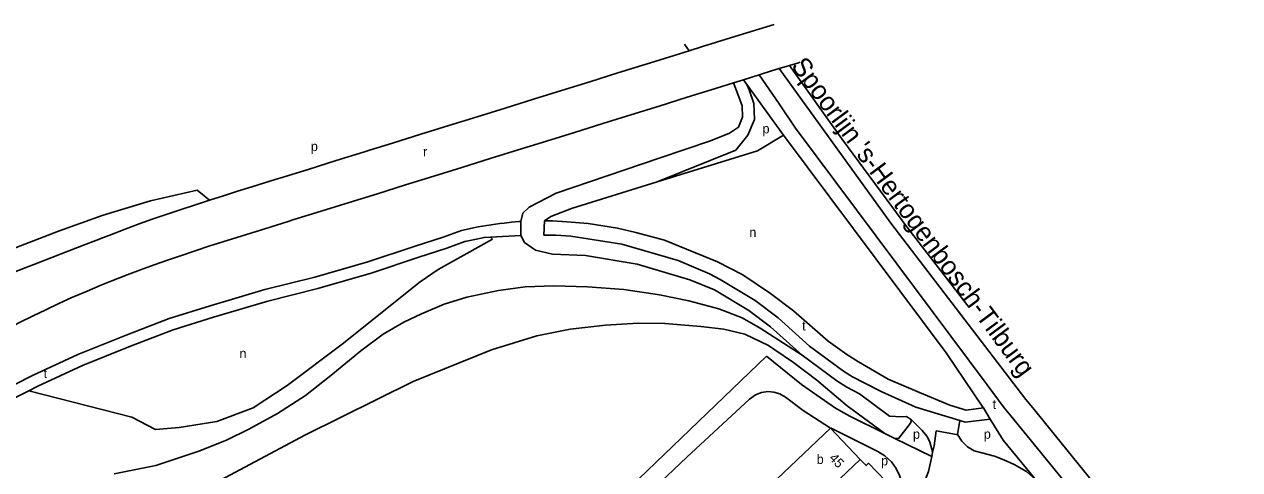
# Model space of a CAD drawing. Extents: x 156097 to 158136, y 385644 to 388348.
# Drawn here: x 156439 to 156955, y 388159 to 388348 of the extents above; entities that cross this region are included whole.
import ezdxf

# ---------------------------------------------------------------- set-up
doc = ezdxf.new("R2010")
doc.units = 0
for name, color, linetype in [('BLT_Basislijn', 7, 'Continuous'), ('BLT_Bebouwing', 7, 'Continuous'), ('BLT_Centroide', 7, 'Continuous'), ('BLT_Huisnummer_zonder_bebouwing', 7, 'Continuous'), ('BLT_Spoorlijn', 7, 'Continuous'), ('BLT_Vlakafsluiter', 7, 'Continuous'), ('BLT_Waternaam_spoorwegen', 7, 'Continuous')]:
    doc.layers.add(name, color=color, linetype=linetype)

msp = doc.modelspace()

# ---------------------------------------------------------------- linework, layer by layer
at = {"layer": 'BLT_Basislijn'}
for p, q in [((156719.27, 388339.5), (156721.23, 388336.66)), ((156740.1, 388323.1), (156744.33, 388324.41)), ((156744.33, 388324.41), (156750.98, 388326.48)), ((156744.33, 388324.41), (156745.73, 388322.47)), ((156745.73, 388322.47), (156761.29, 388300.94)), ((156761.29, 388300.94), (156750.28, 388294.39)), ((156750.28, 388294.39), (156707.78, 388281.17)), ((156707.78, 388281.17), (156671.38, 388269.85)), ((156649.88, 388258.43), (156649.94, 388264.43)), ((156659.75, 388258.63), (156660.01, 388264.72)), ((156634.36, 388257.66), (156637.13, 388257.8)), ((156637.13, 388257.8), (156637.97, 388256.94)), ((156836.05, 388180.16), (156820.66, 388184.84)), ((156838.7, 388184.58), (156846.02, 388185.48)), ((156845.79, 388185.85), (156846.02, 388185.48)), ((156835.07, 388174.23), (156836.05, 388180.16)), ((156838.25, 388179.49), (156848.88, 388180.8)), ((156808.46, 388172.56), (156804.17, 388174.7)), ((156808.46, 388172.56), (156824.09, 388164.9)), ((156824.48, 388166.58), (156824.09, 388164.9))]:
    msp.add_line(p, q, dxfattribs=at)
for points in [[(156721.23, 388336.66), (156726.88, 388338.42), (156738.82, 388342.13), (156750.76, 388345.84), (156757.28, 388347.86)], [(156517.96, 388273.44), (156523.93, 388275.34), (156529.91, 388277.22), (156535.88, 388279.08), (156540.87, 388280.63), (156545.86, 388282.17), (156547.83, 388282.78), (156559.77, 388286.48), (156571.71, 388290.19), (156583.64, 388293.9), (156585.78, 388294.56), (156595.58, 388297.61), (156607.52, 388301.32), (156615.33, 388303.74), (156619.45, 388305.03), (156631.39, 388308.74), (156643.33, 388312.45), (156655.26, 388316.16), (156667.2, 388319.87), (156679.14, 388323.58), (156691.07, 388327.29), (156703.01, 388331), (156714.95, 388334.71), (156721.23, 388336.66)], [(156750.98, 388326.48), (156756.26, 388328.12), (156759.46, 388329.12)], [(156759.46, 388329.12), (156762.84, 388330.16), (156763.75, 388330.45)], [(156763.75, 388330.45), (156767.58, 388331.64), (156768.38, 388331.9)], [(156750.98, 388326.48), (156759.42, 388314.15), (156766.39, 388303.96)], [(156601.09, 388279.89), (156613.02, 388283.6), (156620.83, 388286.03), (156624.96, 388287.31), (156636.9, 388291.02), (156648.83, 388294.73), (156660.77, 388298.44), (156672.71, 388302.15), (156684.64, 388305.86), (156696.58, 388309.57), (156708.52, 388313.28), (156720.45, 388316.99), (156732.39, 388320.7), (156740.1, 388323.1)], [(156740.1, 388323.1), (156741.99, 388318.36), (156743.77, 388313.39), (156743.96, 388308.52), (156742.18, 388304.31), (156738.43, 388301.78), (156730.38, 388298.59), (156708.65, 388291.19), (156664.98, 388276.43)], [(156707.78, 388281.17), (156741.07, 388294.57), (156746.21, 388301), (156749, 388307.6), (156748.74, 388314.36), (156746.67, 388320.13), (156745.73, 388322.47)], [(156766.39, 388303.96), (156809.26, 388246.5), (156847.59, 388195.26), (156854.85, 388185.54), (156857.58, 388182.14), (156915.93, 388110.8)], [(156761.29, 388300.94), (156830.24, 388208.76), (156845.79, 388185.85)], [(156310.15, 388191.73), (156310.04, 388198.76), (156310.36, 388202.13), (156311, 388204.11), (156312.29, 388205.67), (156314.27, 388206.74), (156318.97, 388208.56), (156330.61, 388213.22), (156351.21, 388221.28), (156374.15, 388230.36), (156403.23, 388241.32), (156427.16, 388250.01), (156454.03, 388260.34), (156472.88, 388267.06), (156493.03, 388273.12), (156512.7, 388277.71)], [(156462.79, 388233.54), (156466.12, 388234.99), (156471.72, 388237.34), (156476.63, 388239.32), (156479.82, 388240.57), (156483.03, 388241.8), (156488.74, 388243.94), (156494.49, 388246.03), (156500.26, 388248.06), (156506.07, 388250.05), (156511.91, 388252), (156517.77, 388253.91), (156523.65, 388255.8), (156529.55, 388257.66), (156535.48, 388259.51), (156541.42, 388261.35), (156546.39, 388262.89), (156551.37, 388264.44), (156553.34, 388265.05), (156565.27, 388268.76), (156577.21, 388272.47), (156589.15, 388276.18), (156601.09, 388279.89)], [(156464.62, 388254.39), (156469.78, 388256.39), (156473.1, 388257.68), (156476.42, 388258.96), (156482.31, 388261.19), (156488.21, 388263.38), (156494.14, 388265.48), (156500.08, 388267.53), (156506.03, 388269.54), (156511.99, 388271.5), (156517.96, 388273.44)], [(156649.94, 388264.43), (156650.81, 388267.99), (156653.45, 388270.54), (156664.98, 388276.43)], [(156671.38, 388269.85), (156662.61, 388266.55), (156660.01, 388264.72)], [(156641.1, 388263.55), (156631.88, 388262.15), (156624.81, 388260.67)], [(156649.94, 388264.43), (156649.24, 388264.39), (156646.03, 388264.12), (156642.83, 388263.77), (156641.1, 388263.55)], [(156660.01, 388264.72), (156663.31, 388264.72), (156669.45, 388264.23)], [(156669.45, 388264.23), (156678.55, 388263.51), (156690.98, 388261.56), (156698.71, 388259.79), (156710.8, 388256.45), (156733.28, 388247.33), (156744, 388241.77), (156755.83, 388233.99), (156765.45, 388226.61), (156780.27, 388213.79), (156788.16, 388208.11), (156793.06, 388204.95), (156805.7, 388197.7), (156818.97, 388192)], [(156427.57, 388191.41), (156443.03, 388199.19), (156462.12, 388208.06), (156482.64, 388216.28), (156500.93, 388223.33), (156518.21, 388228.72), (156541.46, 388235.56), (156562.67, 388240.84), (156585.09, 388247.29), (156605.17, 388254.04), (156616.96, 388257.82), (156624.81, 388260.67)], [(156637.97, 388256.94), (156614.85, 388244.16), (156607.25, 388238.83), (156577.69, 388215.26)], [(156626.26, 388255.88), (156630.43, 388256.85), (156634.36, 388257.66)], [(156637.13, 388257.8), (156649.88, 388258.43)], [(156649.88, 388258.43), (156651.52, 388255.54), (156656.21, 388252.27), (156663.42, 388250.6), (156677.4, 388249.96), (156699.31, 388246.33), (156721.51, 388239.77), (156732.07, 388235.52), (156746.53, 388226.77), (156755.82, 388219.8), (156769.15, 388207.79)], [(156659.75, 388258.63), (156664.8, 388258.58), (156671.15, 388258.18), (156692.76, 388254.86), (156716.58, 388247.94), (156729.86, 388242.2), (156734.48, 388239.9), (156749.33, 388230.92), (156759, 388223.67), (156772.31, 388211.67), (156786.74, 388201.07), (156790.57, 388198.68), (156795.8, 388195.98), (156802.67, 388192.51), (156817.36, 388185.88), (156820.66, 388184.84)], [(156422.05, 388237.85), (156433.69, 388242.42), (156445.34, 388246.96), (156457, 388251.46), (156464.62, 388254.39)], [(156441.39, 388192.77), (156445.21, 388194.69), (156464.1, 388203.47), (156484.46, 388211.62), (156502.58, 388218.6), (156519.66, 388223.93), (156542.77, 388230.73), (156563.96, 388236.01), (156586.58, 388242.52), (156606.73, 388249.29), (156618.58, 388253.08), (156626.26, 388255.88)], [(156477.61, 388157.6), (156495.23, 388161.2), (156513.96, 388167.37), (156525.47, 388172.01), (156534.68, 388176.57), (156546.77, 388183.18), (156558.68, 388190.8), (156569.42, 388199.23), (156582.18, 388209.7), (156591.61, 388216.7), (156600.36, 388221.75), (156607.85, 388225.37), (156617.43, 388229.44), (156627.06, 388232.32), (156640.54, 388235.18), (156651.82, 388236.73), (156663.87, 388237.23), (156678.25, 388236.7), (156693.56, 388235.66), (156708.72, 388233.31), (156721.13, 388230.87), (156733.88, 388227.48), (156743.79, 388223.6), (156751.38, 388219.23), (156769.15, 388207.79)], [(156426.98, 388216.11), (156432.35, 388218.95), (156437.75, 388221.74), (156443.19, 388224.45), (156448.66, 388227.09), (156454.16, 388229.67), (156459.69, 388232.18), (156462.79, 388233.54)], [(156485.93, 388134.75), (156520.26, 388153.7), (156558.61, 388174.16), (156604.33, 388196.66), (156637.51, 388210.11), (156656.68, 388216.01), (156670.79, 388218.78), (156685.81, 388220.53), (156699.64, 388221.36), (156710.97, 388221.17), (156726.28, 388219.98), (156736.05, 388218.78), (156744.9, 388216.66), (156754.94, 388211.86), (156757.16, 388210.36)], [(156577.69, 388215.26), (156574.8, 388212.96), (156550.97, 388194.95), (156536.52, 388185.56), (156521.05, 388179.72), (156505.08, 388177.19), (156495.13, 388176.32)], [(156757.16, 388210.36), (156765.54, 388204.67), (156775.41, 388197.21), (156788.31, 388186.33), (156804.17, 388174.7)], [(156568.02, 388054.23), (156575.7, 388061.48), (156570, 388067.47), (156587.67, 388084.27), (156593.59, 388078), (156600.05, 388071.96), (156687.2, 388154.59), (156692.7, 388148.63), (156754.13, 388207.46)], [(156804.17, 388174.7), (156789.45, 388182.06), (156783.37, 388185.41), (156768.89, 388195.44), (156754.13, 388207.46)], [(156769.15, 388207.79), (156783.93, 388196.93), (156788.1, 388194.32), (156793.53, 388191.53), (156806.21, 388182), (156811.42, 388181.72), (156813.38, 388181.91), (156815.49, 388180.4)], [(156338.94, 388124.85), (156340.17, 388124.85), (156344.16, 388125.89), (156348.54, 388128.66), (156355.98, 388135.47), (156366.9, 388144.44), (156381.42, 388154.8), (156392.68, 388163.02), (156404.35, 388171.12), (156417.38, 388179.76), (156429.94, 388187.01), (156441.39, 388192.77)], [(156495.13, 388176.32), (156485.01, 388181.64), (156441.39, 388192.77)], [(156697.98, 388143.49), (156720.27, 388164.66), (156746.9, 388189.19), (156749.43, 388191.03), (156751.92, 388192.01), (156754.57, 388192.42), (156757.24, 388192.23), (156759.79, 388191.42), (156762.12, 388190.08), (156769.66, 388184.41), (156781.26, 388176.99)], [(156838.7, 388184.58), (156831.72, 388186.7), (156818.97, 388192)], [(156815.49, 388180.4), (156815.08, 388179.03), (156810.18, 388172.67), (156808.46, 388172.56)], [(156815.49, 388180.4), (156819.97, 388176.1), (156822.24, 388173.36), (156823.33, 388171.05), (156824.17, 388168.04), (156824.48, 388166.58)], [(156836.05, 388180.16), (156838.26, 388179.49), (156838.26, 388179.49)], [(156868.17, 388155.08), (156854.32, 388171.8), (156848.88, 388180.8)], [(156781.26, 388176.99), (156781.53, 388176.99), (156801.2, 388167.05), (156804.17, 388165.17), (156806.99, 388162.65), (156808.99, 388159.88), (156810.49, 388156.85), (156811.46, 388153.73), (156811.95, 388150.23), (156811.64, 388146.35), (156810.95, 388143.12), (156809.78, 388139.74), (156808.08, 388136.3)], [(156825.95, 388175.74), (156825.13, 388169.4), (156824.48, 388166.58)], [(156825.95, 388175.74), (156834.63, 388174.3), (156835.07, 388174.23)], [(156835.07, 388174.23), (156836.83, 388171.49), (156839.32, 388169.03), (156842.08, 388167.41), (156845.28, 388166.45), (156850.65, 388165.09), (156854.6, 388163.59), (156858.98, 388161.51), (156864.3, 388158.54), (156868.17, 388155.08)], [(156793.82, 388163.73), (156796.31, 388161.1), (156797.34, 388162.08), (156808.14, 388150.79), (156787.31, 388131.01)]]:
    msp.add_lwpolyline(points, dxfattribs=at)
at = {"layer": 'BLT_Bebouwing'}
for p, q in [((156781.26, 388176.99), (156793.82, 388163.73)), ((156793.82, 388163.73), (156776.75, 388147.53))]:
    msp.add_line(p, q, dxfattribs=at)
msp.add_lwpolyline([(156765.37, 388136.74), (156752.81, 388149.97), (156781.26, 388176.99)], dxfattribs=at)
at = {"layer": 'BLT_Spoorlijn'}
for points in [[(156759.46, 388329.12), (156806.82, 388263.75)], [(156763.75, 388330.45), (156786.07, 388299.4), (156814.04, 388261.54)], [(156806.82, 388263.75), (156863.99, 388189.1)], [(156814.04, 388261.54), (156839.98, 388228.04)], [(156863.63, 388189.58), (156863.79, 388189.37)], [(156863.99, 388189.1), (156866.93, 388185.5)], [(156866.93, 388185.5), (156954.63, 388077.33)]]:
    msp.add_lwpolyline(points, dxfattribs=at)
at = {"layer": 'BLT_Vlakafsluiter'}
for p, q in [((156512.7, 388277.71), (156517.96, 388273.44)), ((156846.02, 388185.48), (156848.88, 388180.8))]:
    msp.add_line(p, q, dxfattribs=at)
msp.add_lwpolyline([(156824.09, 388164.9), (156822.78, 388158.6), (156820.51, 388152.83), (156817.85, 388147.89), (156815.04, 388143.79), (156812.38, 388140.57), (156809.93, 388138.05)], dxfattribs=at)

# ---------------------------------------------------------------- texts
at = {"layer": 'BLT_Centroide'}
for s, p in [('p', (156752.38, 388301.7)), ('p', (156560.95, 388294.23)), ('r', (156608.47, 388291.96)), ('n', (156746.81, 388257.87)), ('t', (156769.16, 388218.3)), ('n', (156530.68, 388206.58)), ('t', (156447.71, 388198.13)), ('t', (156849.91, 388185.03)), ('p', (156816.15, 388172.45)), ('p', (156846.18, 388172.45)), ('b', (156775.34, 388161.8)), ('p', (156802.63, 388161.18))]:
    msp.add_text(s, height=4, dxfattribs=at).set_placement(p)
at = {"layer": 'BLT_Huisnummer_zonder_bebouwing'}
msp.add_text('45', height=4, rotation=313.5099, dxfattribs=at).set_placement((156780.34, 388164.04))
at = {"layer": 'BLT_Waternaam_spoorwegen'}
msp.add_text("Spoorlijn 's-Hertogenbosch-Tilburg", height=8, rotation=306.4877, dxfattribs=at).set_placement((156764.21, 388330.21))

doc.saveas('drawing.dxf')
